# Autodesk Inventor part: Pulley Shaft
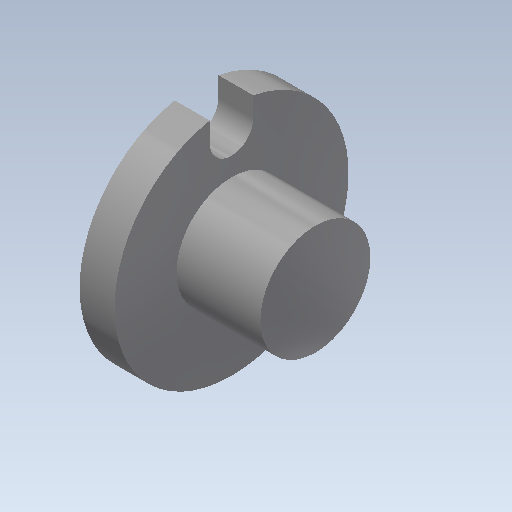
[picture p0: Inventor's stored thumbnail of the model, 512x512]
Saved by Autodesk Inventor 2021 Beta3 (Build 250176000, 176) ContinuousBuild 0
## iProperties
Created: 2012-08
Part Number: Pulley Shaft
Material: Steel
Document SubType Name: Modeling
Designer: John
Mass: 13.0314 g
Surface Area: 11.3717 cm^2
Volume: 1.66006 cm^3
Density: 7.85 g/cm^3
Appearance: Steel
Author: John
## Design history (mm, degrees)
sketch "Sketch1"
  geometry: C1 r 8.509 at (0, 0); 1 further point
  constraints: 1 centre point, 1 coincident
  dimensions: "d1" = 17.018 diameter of C1
extrude "Extrusion1" new body sketch "Sketch1" distance "d3" = 2.54; taper "d4" = 0 deg
sketch "Sketch2"
  geometry: C1 r 8.509 at (0, 0) reference; C2 r 4.001 at (0, 0)
  constraints: 1 centre point, 1 coincident
  dimensions: "d5" = 8.001 diameter of C2
extrude "Extrusion2" join sketch "Sketch2" distance "d6" = 6.096; taper "d7" = 0 deg
sketch "Sketch3"
  geometry: L1 (6.934, -1.587)-(8.36, -1.587); L2 (6.934, 1.588)-(8.36, 1.588); L3 (6.934, 0)-(0, 0); A1 r 8.509 centre (0, 0) between (8.36, -1.587) and (8.36, 1.588) reference; A2 r 1.587 centre (6.934, 0) between (6.934, -1.587) and (6.934, 1.588)
  constraints: 6 end point, 4 point on circle, 2 parallel, 2 tangent, 1 centre point, 1 horizontal
  dimensions: "d8" = 6.9342 distance of L3.start L3.end; "d9" = 3.175 diameter of A2
extrude "Extrusion3" cut sketch "Sketch3" extent not by distance; stored distance "d10" = 21.971; taper "d11" = 0 deg
body "Solid1"
